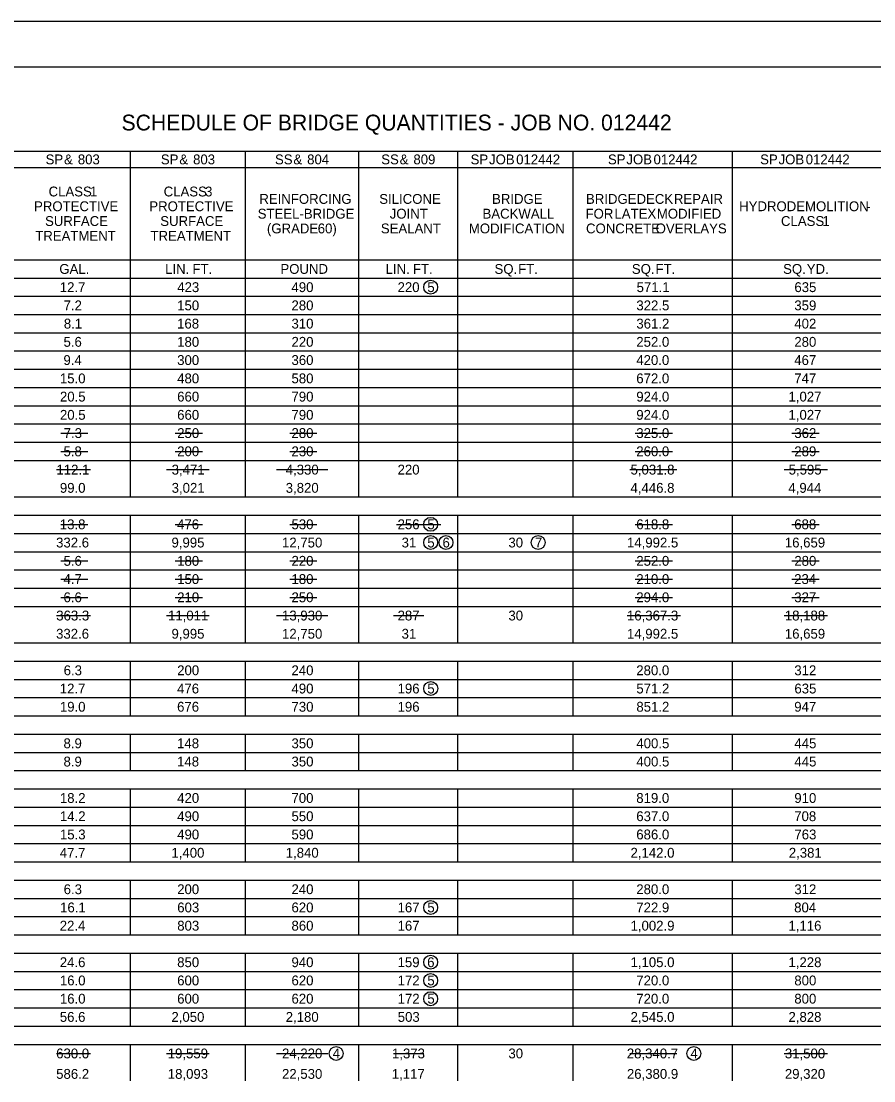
# Model space of a CAD drawing. Extents: x 18 to 14744716, y -5 to 1829144.
# Drawn here: x 30.4 to 41.2, y 3.2 to 16.63 of the extents above; entities that cross this region are included whole.
import ezdxf

# ---------------------------------------------------------------- set-up
doc = ezdxf.new("R2010")
doc.units = 0
for name, color, linetype in [('B_Dimensions', 7, 'Continuous'), ('B_Text', 7, 'Continuous'), ('B_Title Text', 7, 'Continuous'), ('R_Border', 7, 'Continuous'), ('R_No Plot', 7, 'Continuous')]:
    doc.layers.add(name, color=color, linetype=linetype)

msp = doc.modelspace()

# ---------------------------------------------------------------- linework, layer by layer
at = {"layer": 'B_Dimensions'}
for p, q in [((30.898, 11.408), (31.241, 11.408)), ((32.348, 11.408), (32.691, 11.408)), ((33.797, 11.408), (34.14, 11.408)), ((38.172, 11.408), (38.648, 11.408)), ((40.16, 11.408), (40.503, 11.408)), ((30.898, 11.177), (31.241, 11.177)), ((32.348, 11.177), (32.691, 11.177)), ((33.797, 11.177), (34.14, 11.177)), ((38.172, 11.177), (38.648, 11.177)), ((40.16, 11.177), (40.503, 11.177)), ((30.842, 10.946), (31.273, 10.946)), ((32.237, 10.946), (32.779, 10.946)), ((33.63, 10.946), (34.281, 10.946)), ((38.105, 10.946), (38.7, 10.946)), ((40.061, 10.946), (40.611, 10.946)), ((30.898, 10.252), (31.241, 10.252)), ((32.348, 10.252), (32.691, 10.252)), ((33.797, 10.252), (34.14, 10.252)), ((35.151, 10.252), (35.714, 10.252)), ((38.172, 10.252), (38.648, 10.252)), ((40.16, 10.252), (40.503, 10.252)), ((30.898, 9.79), (31.241, 9.79)), ((32.348, 9.79), (32.691, 9.79)), ((33.797, 9.79), (34.14, 9.79)), ((38.172, 9.79), (38.648, 9.79)), ((40.16, 9.79), (40.503, 9.79)), ((30.898, 9.559), (31.241, 9.559)), ((32.348, 9.559), (32.691, 9.559)), ((33.797, 9.559), (34.14, 9.559)), ((38.172, 9.559), (38.648, 9.559)), ((40.16, 9.559), (40.503, 9.559)), ((30.898, 9.327), (31.241, 9.327)), ((32.348, 9.327), (32.691, 9.327)), ((33.797, 9.327), (34.14, 9.327)), ((38.172, 9.327), (38.648, 9.327)), ((40.16, 9.327), (40.503, 9.327)), ((30.842, 9.096), (31.273, 9.096)), ((32.237, 9.096), (32.779, 9.096)), ((33.63, 9.096), (34.281, 9.096)), ((35.113, 9.096), (35.498, 9.096)), ((38.071, 9.096), (38.748, 9.096)), ((40.061, 9.096), (40.611, 9.096)), ((30.842, 3.548), (31.273, 3.548)), ((32.237, 3.548), (32.779, 3.548)), ((33.63, 3.548), (34.281, 3.548)), ((35.113, 3.548), (35.498, 3.548)), ((38.105, 3.548), (38.7, 3.548)), ((40.061, 3.548), (40.611, 3.548))]:
    msp.add_line(p, q, dxfattribs=at)
for centre in [(35.583, 13.258), (35.583, 10.252), (35.583, 10.021), (35.777, 10.021), (36.944, 10.021), (35.584, 8.171), (35.583, 5.397), (35.583, 4.704), (35.583, 4.472), (35.583, 4.241), (34.386, 3.548), (38.918, 3.548)]:
    msp.add_circle(centre, 0.0881, dxfattribs=at)
at = {"layer": 'B_Text'}
for p, q in [((19.392, 14.979), (51.101, 14.979)), ((31.779, 10.599), (31.779, 14.979)), ((33.239, 10.599), (33.239, 14.979)), ((34.675, 10.599), (34.675, 14.979)), ((35.928, 10.599), (35.928, 14.979)), ((37.388, 10.599), (37.388, 14.979)), ((39.408, 10.599), (39.408, 14.979)), ((27.569, 14.773), (51.101, 14.773)), ((27.569, 13.604), (51.101, 13.604)), ((19.392, 13.373), (51.101, 13.373)), ((20.304, 13.142), (51.101, 13.142)), ((20.304, 12.911), (51.101, 12.911)), ((20.304, 12.68), (51.101, 12.68)), ((20.304, 12.449), (51.101, 12.449)), ((20.304, 12.217), (51.101, 12.217)), ((20.304, 11.986), (51.101, 11.986)), ((20.304, 11.755), (51.101, 11.755)), ((20.304, 11.524), (51.101, 11.524)), ((20.304, 11.293), (51.101, 11.293)), ((20.304, 11.061), (51.101, 11.061)), ((19.392, 10.599), (51.101, 10.599)), ((19.392, 10.368), (51.101, 10.368)), ((31.779, 8.749), (31.779, 10.368)), ((33.239, 8.749), (33.239, 10.368)), ((34.675, 8.749), (34.675, 10.368)), ((35.928, 8.749), (35.928, 10.368)), ((37.388, 8.749), (37.388, 10.368)), ((39.408, 8.749), (39.408, 10.368)), ((20.304, 10.137), (51.101, 10.137)), ((20.304, 9.905), (51.101, 9.905)), ((20.304, 9.674), (51.101, 9.674)), ((20.304, 9.443), (51.101, 9.443)), ((20.304, 9.212), (51.101, 9.212)), ((19.392, 8.749), (51.101, 8.749)), ((19.392, 8.518), (46.392, 8.518)), ((19.392, 8.518), (44.823, 8.518)), ((31.779, 7.825), (31.779, 8.518)), ((33.239, 7.825), (33.239, 8.518)), ((34.675, 7.825), (34.675, 8.518)), ((35.928, 7.825), (35.928, 8.518)), ((37.388, 7.825), (37.388, 8.518)), ((39.408, 7.825), (39.408, 8.518)), ((20.304, 8.287), (51.101, 8.287)), ((20.304, 8.056), (51.101, 8.056)), ((19.392, 7.825), (51.101, 7.825)), ((19.392, 7.593), (46.392, 7.593)), ((19.392, 7.593), (44.823, 7.593)), ((31.779, 7.131), (31.779, 7.593)), ((33.239, 7.131), (33.239, 7.593)), ((34.675, 7.131), (34.675, 7.593)), ((35.928, 7.131), (35.928, 7.593)), ((37.388, 7.131), (37.388, 7.593)), ((39.408, 7.131), (39.408, 7.593)), ((20.304, 7.362), (51.101, 7.362)), ((19.392, 7.131), (51.101, 7.131)), ((19.392, 6.9), (46.392, 6.9)), ((19.392, 6.9), (44.823, 6.9)), ((31.779, 5.975), (31.779, 6.9)), ((33.239, 5.975), (33.239, 6.9)), ((34.675, 5.975), (34.675, 6.9)), ((35.928, 5.975), (35.928, 6.9)), ((37.388, 5.975), (37.388, 6.9)), ((39.408, 5.975), (39.408, 6.9)), ((20.304, 6.669), (51.101, 6.669)), ((20.304, 6.438), (51.101, 6.438)), ((20.304, 6.206), (51.101, 6.206)), ((19.392, 5.975), (51.101, 5.975)), ((19.392, 5.744), (46.392, 5.744)), ((19.392, 5.744), (44.823, 5.744)), ((31.779, 5.05), (31.779, 5.744)), ((33.239, 5.05), (33.239, 5.744)), ((34.675, 5.05), (34.675, 5.744)), ((35.928, 5.05), (35.928, 5.744)), ((37.388, 5.05), (37.388, 5.744)), ((39.408, 5.05), (39.408, 5.744)), ((20.304, 5.513), (51.101, 5.513)), ((20.304, 5.282), (51.101, 5.282)), ((19.392, 5.05), (51.101, 5.05)), ((19.392, 4.819), (46.392, 4.819)), ((19.392, 4.819), (44.823, 4.819)), ((31.779, 3.894), (31.779, 4.819)), ((33.239, 3.894), (33.239, 4.819)), ((34.675, 3.894), (34.675, 4.819)), ((35.928, 3.894), (35.928, 4.819)), ((37.388, 3.894), (37.388, 4.819)), ((39.408, 3.894), (39.408, 4.819)), ((20.304, 4.588), (51.101, 4.588)), ((20.304, 4.357), (51.101, 4.357)), ((20.304, 4.126), (51.101, 4.126)), ((19.392, 3.894), (51.101, 3.894)), ((19.392, 3.663), (46.392, 3.663)), ((19.392, 3.663), (44.823, 3.663)), ((31.779, 3.201), (31.779, 3.663)), ((33.239, 3.201), (33.239, 3.663)), ((34.675, 3.201), (34.675, 3.663)), ((35.928, 3.201), (35.928, 3.663)), ((37.388, 3.201), (37.388, 3.663)), ((39.408, 3.201), (39.408, 3.663))]:
    msp.add_line(p, q, dxfattribs=at)
at = {"layer": 'R_Border'}
msp.add_line((19.293, 16.051), (51.2, 16.051), dxfattribs=at)
at = {"layer": 'R_No Plot'}
msp.add_lwpolyline([(17.777, 16.628), (51.777, 16.628), (51.777, -5.372), (17.777, -5.372)], close=True, dxfattribs=at)

# ---------------------------------------------------------------- texts
at = {"layer": 'B_Text'}
for s, height, p in [('SP', 0.1248, (30.705, 14.814)), (' &', 0.1248, (30.892, 14.814)), (' 803', 0.1248, (31.067, 14.814)), ('SP', 0.1248, (32.165, 14.814)), (' &', 0.1248, (32.353, 14.814)), (' 803', 0.1248, (32.527, 14.814)), ('SS', 0.1248, (33.611, 14.814)), (' &', 0.1248, (33.798, 14.814)), (' 804', 0.1248, (33.972, 14.814)), ('SS', 0.1248, (34.957, 14.814)), (' &', 0.1248, (35.144, 14.814)), (' 809', 0.1248, (35.318, 14.814)), ('SP', 0.1248, (36.089, 14.814)), (' JOB', 0.1248, (36.276, 14.814)), (' 012442', 0.1248, (36.62, 14.814)), ('SP', 0.1248, (37.829, 14.814)), (' JOB', 0.1248, (38.016, 14.814)), (' 012442', 0.1248, (38.36, 14.814)), ('SP', 0.1248, (39.757, 14.814)), (' JOB', 0.1248, (39.944, 14.814)), (' 012442', 0.1248, (40.288, 14.814)), ('CLASS', 0.1248, (30.743, 14.407)), (' 1', 0.1248, (31.221, 14.407)), ('CLASS', 0.1248, (32.201, 14.407)), (' 3', 0.1248, (32.679, 14.407)), ('REINFORCING', 0.1248, (33.413, 14.313)), ('SILICONE', 0.1248, (34.932, 14.313)), ('BRIDGE', 0.1248, (36.361, 14.313)), ('BRIDGE', 0.1248, (37.551, 14.313)), (' DECK', 0.1248, (38.145, 14.313)), (' REPAIR', 0.1248, (38.618, 14.313)), ('PROTECTIVE', 0.1248, (30.559, 14.22)), ('PROTECTIVE', 0.1248, (32.019, 14.22)), ('STEEL-BRIDGE', 0.1248, (33.392, 14.126)), ('JOINT', 0.1248, (35.065, 14.126)), ('BACKWALL', 0.1248, (36.24, 14.126)), ('FOR', 0.1248, (37.545, 14.126)), (' LATEX', 0.1248, (37.865, 14.126)), (' MODIFIED', 0.1248, (38.402, 14.126)), ('HYDRODEMOLITION', 0.1248, (39.491, 14.22)), (' -', 0.1248, (41.054, 14.22)), ('SURFACE', 0.1248, (30.698, 14.033)), ('SURFACE', 0.1248, (32.158, 14.033)), ('CLASS', 0.1248, (40.021, 14.033)), (' 1', 0.1248, (40.499, 14.033)), ('TREATMENT', 0.1248, (30.574, 13.845)), ('TREATMENT', 0.1248, (32.034, 13.845)), ('(GRADE', 0.1248, (33.509, 13.939)), (' 60)', 0.1248, (34.106, 13.939)), ('SEALANT', 0.1248, (34.952, 13.939)), ('MODIFICATION', 0.1248, (36.067, 13.939)), ('CONCRETE', 0.1248, (37.551, 13.939)), (' OVERLAYS', 0.1248, (38.387, 13.939)), ('GAL.', 0.1248, (30.879, 13.426)), ('LIN.', 0.1248, (32.219, 13.426)), (' FT.', 0.1248, (32.519, 13.426)), ('POUND', 0.1248, (33.68, 13.426)), ('LIN.', 0.1248, (35.012, 13.426)), (' FT.', 0.1248, (35.312, 13.426)), ('SQ.', 0.1248, (36.392, 13.426)), (' FT.', 0.1248, (36.645, 13.426)), ('SQ.', 0.1248, (38.132, 13.426)), (' FT.', 0.1248, (38.385, 13.426)), ('SQ.', 0.1248, (40.048, 13.426)), (' YD.', 0.1248, (40.301, 13.426)), ('12.7', 0.1248, (30.885, 13.195)), ('423', 0.1248, (32.373, 13.195)), ('490', 0.1248, (33.82, 13.195)), ('220', 0.1248, (35.164, 13.195)), ('5', 0.125, (35.541, 13.195)), ('571.1', 0.1248, (38.192, 13.195)), ('635', 0.1248, (40.191, 13.195)), ('7.2', 0.1248, (30.933, 12.964)), ('150', 0.1248, (32.372, 12.964)), ('280', 0.1248, (33.82, 12.964)), ('322.5', 0.1248, (38.189, 12.964)), ('359', 0.1248, (40.19, 12.964)), ('8.1', 0.1248, (30.936, 12.733)), ('168', 0.1248, (32.371, 12.733)), ('310', 0.1248, (33.82, 12.733)), ('361.2', 0.1248, (38.189, 12.733)), ('402', 0.1248, (40.19, 12.733)), ('5.6', 0.1248, (30.932, 12.502)), ('180', 0.1248, (32.372, 12.502)), ('220', 0.1248, (33.82, 12.502)), ('252.0', 0.1248, (38.188, 12.502)), ('280', 0.1248, (40.19, 12.502)), ('9.4', 0.1248, (30.931, 12.271)), ('300', 0.1248, (32.372, 12.271)), ('360', 0.1248, (33.82, 12.271)), ('420.0', 0.1248, (38.188, 12.271)), ('467', 0.1248, (40.189, 12.271)), ('15.0', 0.1248, (30.886, 12.039)), ('480', 0.1248, (32.372, 12.039)), ('580', 0.1248, (33.82, 12.039)), ('672.0', 0.1248, (38.188, 12.039)), ('747', 0.1248, (40.189, 12.039)), ('20.5', 0.1248, (30.887, 11.808)), ('660', 0.1248, (32.372, 11.808)), ('790', 0.1248, (33.82, 11.808)), ('924.0', 0.1248, (38.188, 11.808)), ('1,027', 0.1248, (40.116, 11.808)), ('20.5', 0.1248, (30.887, 11.577)), ('660', 0.1248, (32.372, 11.577)), ('790', 0.1248, (33.82, 11.577)), ('924.0', 0.1248, (38.188, 11.577)), ('1,027', 0.1248, (40.116, 11.577)), ('7.3', 0.1248, (30.934, 11.346)), ('250', 0.1248, (32.372, 11.346)), ('280', 0.1248, (33.82, 11.346)), ('325.0', 0.1248, (38.188, 11.346)), ('362', 0.1248, (40.19, 11.346)), ('5.8', 0.1248, (30.932, 11.115)), ('200', 0.1248, (32.372, 11.115)), ('230', 0.1248, (33.82, 11.115)), ('260.0', 0.1248, (38.188, 11.115)), ('289', 0.1248, (40.19, 11.115)), ('112.1', 0.1248, (30.842, 10.883)), ('3,471', 0.1248, (32.302, 10.883)), ('4,330', 0.1248, (33.747, 10.883)), ('220', 0.1248, (35.164, 10.883)), ('5,031.8', 0.1248, (38.115, 10.883)), ('5,595', 0.1248, (40.118, 10.883)), ('99.0', 0.1248, (30.886, 10.652)), ('3,021', 0.1248, (32.302, 10.652)), ('3,820', 0.1248, (33.747, 10.652)), ('4,446.8', 0.1248, (38.115, 10.652)), ('4,944', 0.1248, (40.115, 10.652)), ('13.8', 0.1248, (30.885, 10.19)), ('476', 0.1248, (32.371, 10.19)), ('530', 0.1248, (33.82, 10.19)), ('256', 0.1248, (35.164, 10.19)), ('5', 0.125, (35.541, 10.19)), ('618.8', 0.1248, (38.188, 10.19)), ('688', 0.1248, (40.189, 10.19)), ('332.6', 0.1248, (30.838, 9.959)), ('9,995', 0.1248, (32.3, 9.959)), ('12,750', 0.1248, (33.7, 9.959)), ('31', 0.1248, (35.215, 9.959)), ('5', 0.125, (35.541, 9.959)), ('6', 0.125, (35.733, 9.959)), ('30', 0.1248, (36.568, 9.959)), ('7', 0.125, (36.904, 9.959)), ('14,992.5', 0.1248, (38.07, 9.959)), ('16,659', 0.1248, (40.07, 9.959)), ('5.6', 0.1248, (30.932, 9.727)), ('180', 0.1248, (32.372, 9.727)), ('220', 0.1248, (33.82, 9.727)), ('252.0', 0.1248, (38.188, 9.727)), ('280', 0.1248, (40.19, 9.727)), ('4.7', 0.1248, (30.932, 9.496)), ('150', 0.1248, (32.372, 9.496)), ('180', 0.1248, (33.82, 9.496)), ('210.0', 0.1248, (38.188, 9.496)), ('234', 0.1248, (40.188, 9.496)), ('6.6', 0.1248, (30.932, 9.265)), ('210', 0.1248, (32.372, 9.265)), ('250', 0.1248, (33.82, 9.265)), ('294.0', 0.1248, (38.188, 9.265)), ('327', 0.1248, (40.189, 9.265)), ('363.3', 0.1248, (30.84, 9.034)), ('11,011', 0.1248, (32.256, 9.034)), ('13,930', 0.1248, (33.7, 9.034)), ('287', 0.1248, (35.164, 9.034)), ('30', 0.1248, (36.568, 9.034)), ('16,367.3', 0.1248, (38.07, 9.034)), ('18,188', 0.1248, (40.07, 9.034)), ('332.6', 0.1248, (30.838, 8.803)), ('9,995', 0.1248, (32.3, 8.803)), ('12,750', 0.1248, (33.7, 8.803)), ('31', 0.1248, (35.215, 8.803)), ('14,992.5', 0.1248, (38.07, 8.803)), ('16,659', 0.1248, (40.07, 8.803)), ('6.3', 0.1248, (30.934, 8.34)), ('200', 0.1248, (32.372, 8.34)), ('240', 0.1248, (33.82, 8.34)), ('280.0', 0.1248, (38.188, 8.34)), ('312', 0.1248, (40.19, 8.34)), ('12.7', 0.1248, (30.885, 8.109)), ('476', 0.1248, (32.371, 8.109)), ('490', 0.1248, (33.82, 8.109)), ('196', 0.1248, (35.164, 8.109)), ('5', 0.125, (35.541, 8.109)), ('571.2', 0.1248, (38.189, 8.109)), ('635', 0.1248, (40.191, 8.109)), ('19.0', 0.1248, (30.886, 7.878)), ('676', 0.1248, (32.371, 7.878)), ('730', 0.1248, (33.82, 7.878)), ('196', 0.1248, (35.164, 7.878)), ('851.2', 0.1248, (38.189, 7.878)), ('947', 0.1248, (40.189, 7.878)), ('8.9', 0.1248, (30.932, 7.415)), ('148', 0.1248, (32.371, 7.415)), ('350', 0.1248, (33.82, 7.415)), ('400.5', 0.1248, (38.189, 7.415)), ('445', 0.1248, (40.191, 7.415)), ('8.9', 0.1248, (30.932, 7.184)), ('148', 0.1248, (32.371, 7.184)), ('350', 0.1248, (33.82, 7.184)), ('400.5', 0.1248, (38.189, 7.184)), ('445', 0.1248, (40.191, 7.184)), ('18.2', 0.1248, (30.886, 6.722)), ('420', 0.1248, (32.372, 6.722)), ('700', 0.1248, (33.82, 6.722)), ('819.0', 0.1248, (38.188, 6.722)), ('910', 0.1248, (40.19, 6.722)), ('14.2', 0.1248, (30.886, 6.491)), ('490', 0.1248, (32.372, 6.491)), ('550', 0.1248, (33.82, 6.491)), ('637.0', 0.1248, (38.188, 6.491)), ('708', 0.1248, (40.189, 6.491)), ('15.3', 0.1248, (30.887, 6.26)), ('490', 0.1248, (32.372, 6.26)), ('590', 0.1248, (33.82, 6.26)), ('686.0', 0.1248, (38.188, 6.26)), ('763', 0.1248, (40.191, 6.26)), ('47.7', 0.1248, (30.885, 6.028)), ('1,400', 0.1248, (32.299, 6.028)), ('1,840', 0.1248, (33.747, 6.028)), ('2,142.0', 0.1248, (38.115, 6.028)), ('2,381', 0.1248, (40.12, 6.028)), ('6.3', 0.1248, (30.934, 5.566)), ('200', 0.1248, (32.372, 5.566)), ('240', 0.1248, (33.82, 5.566)), ('280.0', 0.1248, (38.188, 5.566)), ('312', 0.1248, (40.19, 5.566)), ('16.1', 0.1248, (30.889, 5.335)), ('603', 0.1248, (32.373, 5.335)), ('620', 0.1248, (33.82, 5.335)), ('167', 0.1248, (35.164, 5.335)), ('5', 0.125, (35.541, 5.335)), ('722.9', 0.1248, (38.188, 5.335)), ('804', 0.1248, (40.188, 5.335)), ('22.4', 0.1248, (30.884, 5.104)), ('803', 0.1248, (32.373, 5.104)), ('860', 0.1248, (33.82, 5.104)), ('167', 0.1248, (35.164, 5.104)), ('1,002.9', 0.1248, (38.115, 5.104)), ('1,116', 0.1248, (40.116, 5.104)), ('24.6', 0.1248, (30.885, 4.641)), ('850', 0.1248, (32.372, 4.641)), ('940', 0.1248, (33.82, 4.641)), ('159', 0.1248, (35.164, 4.641)), ('6', 0.125, (35.539, 4.641)), ('1,105.0', 0.1248, (38.115, 4.641)), ('1,228', 0.1248, (40.116, 4.641)), ('16.0', 0.1248, (30.886, 4.41)), ('600', 0.1248, (32.372, 4.41)), ('620', 0.1248, (33.82, 4.41)), ('172', 0.1248, (35.165, 4.41)), ('5', 0.125, (35.541, 4.41)), ('720.0', 0.1248, (38.188, 4.41)), ('800', 0.1248, (40.19, 4.41)), ('16.0', 0.1248, (30.886, 4.179)), ('600', 0.1248, (32.372, 4.179)), ('620', 0.1248, (33.82, 4.179)), ('172', 0.1248, (35.165, 4.179)), ('5', 0.125, (35.541, 4.179)), ('720.0', 0.1248, (38.188, 4.179)), ('800', 0.1248, (40.19, 4.179)), ('56.6', 0.1248, (30.885, 3.948)), ('2,050', 0.1248, (32.299, 3.948)), ('2,180', 0.1248, (33.747, 3.948)), ('503', 0.1248, (35.166, 3.948)), ('2,545.0', 0.1248, (38.115, 3.948)), ('2,828', 0.1248, (40.116, 3.948)), ('630.0', 0.1248, (30.839, 3.485)), ('19,559', 0.1248, (32.252, 3.485)), ('24,220', 0.1248, (33.7, 3.485)), ('4', 0.125, (34.341, 3.485)), ('1,373', 0.1248, (35.093, 3.485)), ('30', 0.1248, (36.568, 3.485)), ('28,340.7', 0.1248, (38.068, 3.485)), ('4', 0.125, (38.874, 3.485)), ('31,500', 0.1248, (40.07, 3.485)), ('586.2', 0.1248, (30.839, 3.226)), ('18,093', 0.1248, (32.253, 3.226)), ('22,530', 0.1248, (33.7, 3.226)), ('1,117', 0.1248, (35.091, 3.226)), ('26,380.9', 0.1248, (38.069, 3.226)), ('29,320', 0.1248, (40.07, 3.226))]:
    msp.add_text(s, height=height, dxfattribs=at).set_placement(p)
at = {"layer": 'B_Title Text'}
msp.add_text('SCHEDULE OF BRIDGE QUANTITIES - JOB NO. 012442', height=0.2004, dxfattribs=at).set_placement((31.667, 15.243))

doc.saveas('drawing.dxf')
